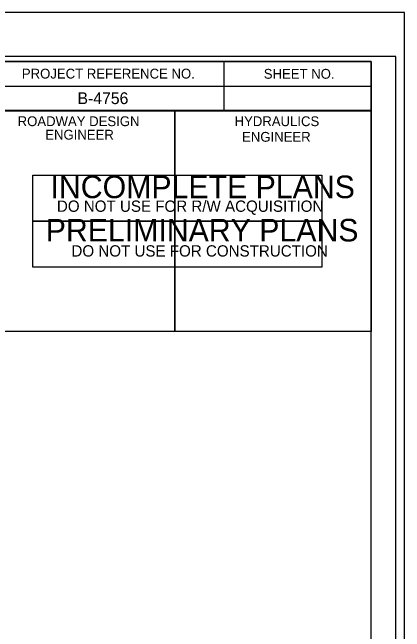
# Model space of a CAD drawing. Extents: x 2431000 to 2534000, y 645879 to 714000.
# Drawn here: x 2468392.6 to 2468592.2, y 662058 to 662373.5 of the extents above; entities that cross this region are included whole.
import ezdxf

# ---------------------------------------------------------------- set-up
doc = ezdxf.new("R2010")
doc.units = 0
for name, color, linetype in [('KHA_LOGO', 7, 'Continuous'), ('Old_Level_2', 7, 'Continuous'), ('Prop Dimension', 7, 'Continuous'), ('Prop Dimension Text', 7, 'Continuous'), ('Prop Terminator CELL', 7, 'Continuous')]:
    doc.layers.add(name, color=color, linetype=linetype)

msp = doc.modelspace()

# ---------------------------------------------------------------- linework, layer by layer
at = {"layer": 'KHA_LOGO'}
for points in [[(2468375.19, 662323.36), (2468475.24, 662323.36), (2468475.24, 662210.86), (2468375.19, 662210.86)], [(2468475.24, 662323.36), (2468575.24, 662323.36), (2468575.24, 662210.86), (2468475.24, 662210.86)]]:
    msp.add_lwpolyline(points, close=True, dxfattribs=at)
at = {"layer": 'Old_Level_2'}
for p, q in [((2468500.24, 662348.41), (2468500.24, 662323.41)), ((2468375.19, 662335.91), (2468575.24, 662335.91))]:
    msp.add_line(p, q, dxfattribs=at)
for points in [[(2468575.24, 662348.46), (2467075.24, 662348.46), (2467075.24, 661298.46), (2468575.24, 661298.46)], [(2468375.19, 662348.46), (2468575.24, 662348.46), (2468575.24, 662323.41), (2468375.19, 662323.41)]]:
    msp.add_lwpolyline(points, close=True, dxfattribs=at)
at = {"layer": 'Prop Dimension'}
msp.add_lwpolyline([(2466908.74, 661273.46), (2468592.24, 661273.46), (2468592.24, 662373.46), (2466908.74, 662373.46)], close=True, dxfattribs=at)
at = {"layer": 'Prop Dimension Text'}
for points in [[(2468403.03, 662267.11), (2468403.03, 662290.61), (2468550.03, 662290.61), (2468550.03, 662267.12)], [(2468403.03, 662243.62), (2468403.03, 662267.11), (2468550.03, 662267.12), (2468550.03, 662243.62)]]:
    msp.add_lwpolyline(points, close=True, dxfattribs=at)
at = {"layer": 'Prop Terminator CELL'}
msp.add_lwpolyline([(2466921.74, 661295.96), (2468587.74, 661295.96), (2468587.74, 662350.96), (2466921.74, 662350.96)], close=True, dxfattribs=at)

# ---------------------------------------------------------------- texts
at = {"layer": 'KHA_LOGO'}
for s, height, p in [('B-4756', 6, (2468425.73, 662326.75)), ('HYDRAULICS', 5, (2468505.69, 662315.51)), ('ENGINEER', 5, (2468509.49, 662307.56))]:
    msp.add_text(s, height=height, dxfattribs=at).set_placement(p)
at = {"layer": 'Old_Level_2'}
for s, height, p in [('PROJECT REFERENCE NO.', 5.0001, (2468397.39, 662339.76)), ('SHEET NO.', 5, (2468520.54, 662339.66)), ('ROADWAY DESIGN', 5.0001, (2468395.24, 662315.51)), ('ENGINEER', 5, (2468409.29, 662308.66))]:
    msp.add_text(s, height=height, dxfattribs=at).set_placement(p)
at = {"layer": 'Prop Dimension Text'}
for s, height, p in [('INCOMPLETE PLANS', 11.52, (2468411.98, 662278.82)), ('DO NOT USE FOR R/W ACQUISITION', 5.76, (2468415.23, 662271.86)), ('PRELIMINARY PLANS', 11.52, (2468409.53, 662256.76)), ('DO NOT USE FOR CONSTRUCTION', 5.76, (2468422.63, 662249.07))]:
    msp.add_text(s, height=height, dxfattribs=at).set_placement(p)

doc.saveas('drawing.dxf')
